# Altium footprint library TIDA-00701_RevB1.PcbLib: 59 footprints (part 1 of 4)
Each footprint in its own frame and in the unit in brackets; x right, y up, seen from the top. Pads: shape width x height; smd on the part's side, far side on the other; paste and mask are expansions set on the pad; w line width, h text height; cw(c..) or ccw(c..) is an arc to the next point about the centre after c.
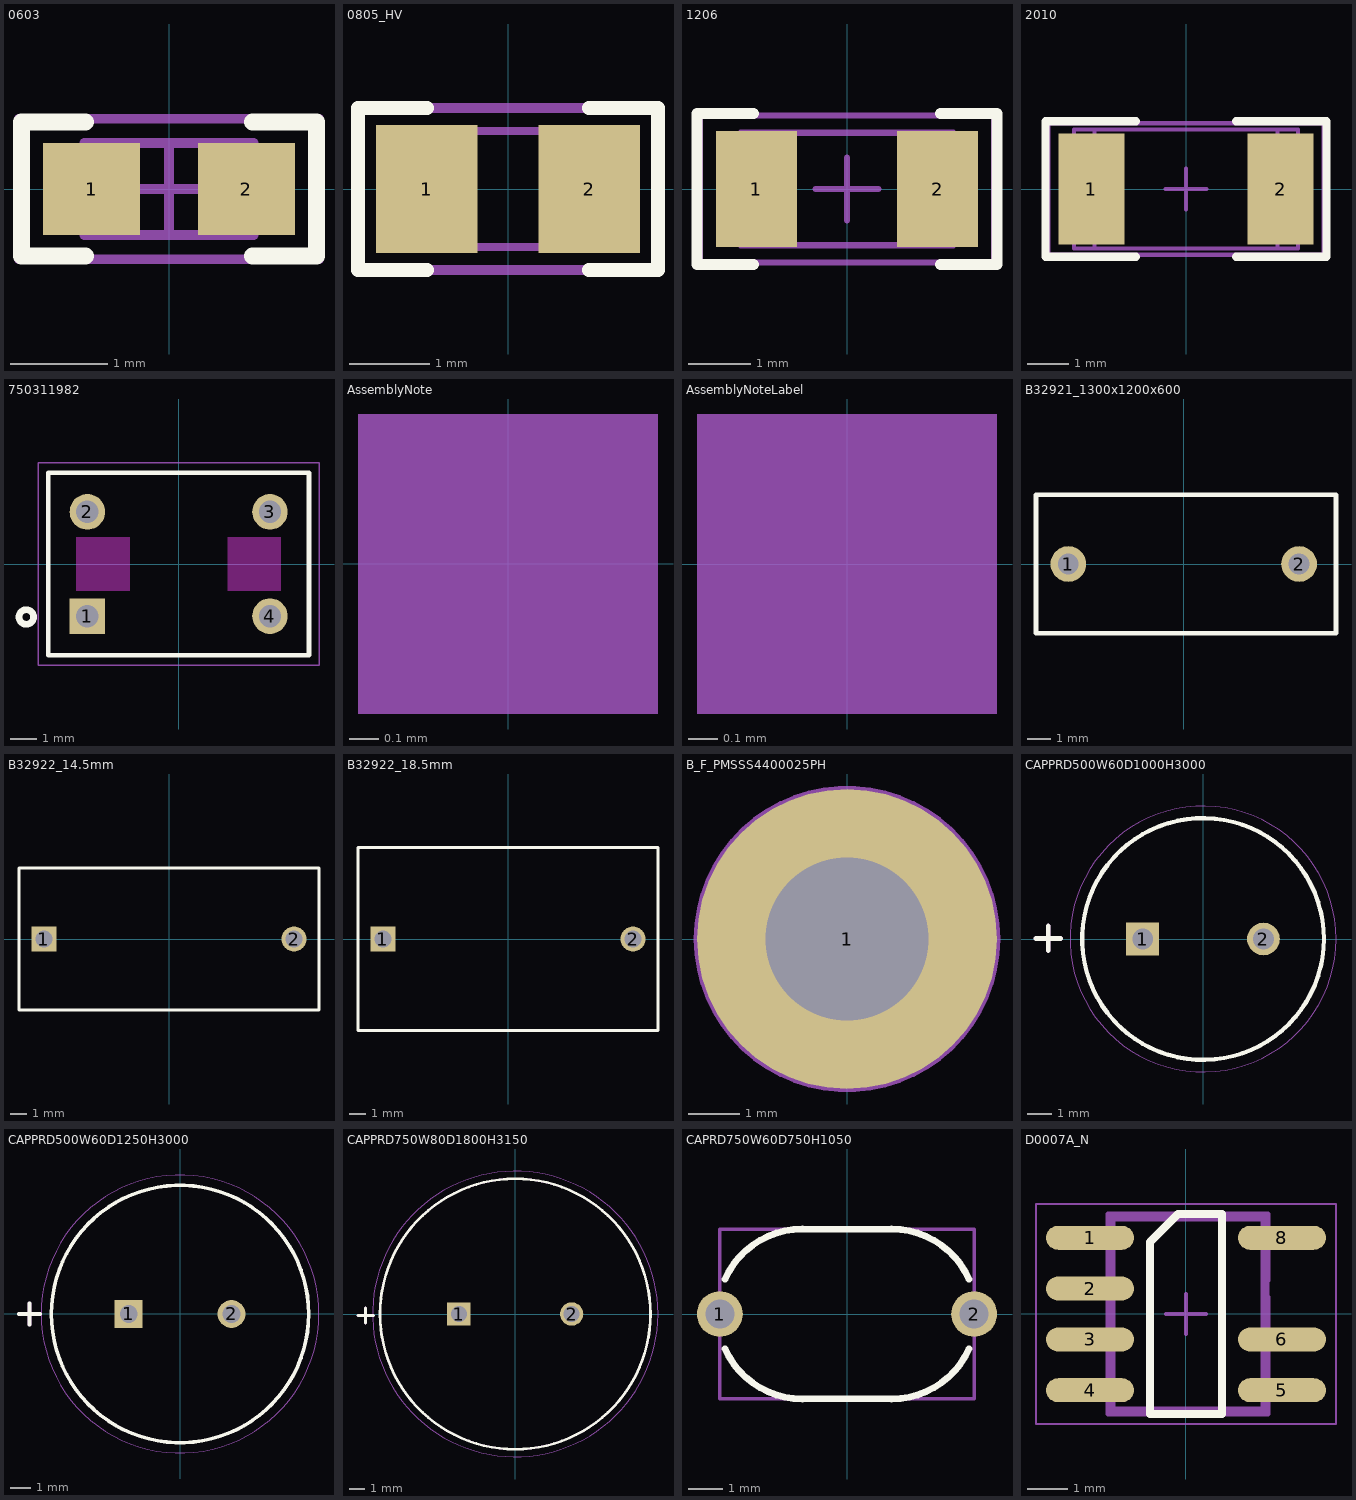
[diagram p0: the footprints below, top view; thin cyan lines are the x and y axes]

## 0603 [mm] "0603 from SM-752 data"
height 1
pads (2):
  rect 1x0.95 smd: 1(-0.8,0) 2(0.8,0)
Top Overlay:
  lines w0.178: -0.864,-0.691 -1.524,-0.691 -1.524,0.693 -0.864,0.693 ; 0.864,-0.691 1.524,-0.691 1.524,0.693 0.864,0.693
Mechanical 5:
  lines w0.1: -1.55,-0.725 -1.55,0.725 1.55,0.725 1.55,-0.725 -1.55,-0.725
  text ".Designator" at -1.168,-0.432 h0.86
Mechanical 13:
  lines w0.1: -0.55,-0.475 -0.55,0.475 ; 0.55,-0.475 0.55,0.475 ; -0.875,-0.475 0.875,-0.475 0.875,0.475 -0.875,0.475 -0.875,-0.475
Mechanical 15:
  lines w0.1: -0.475,0 0.475,0 ; 0,-0.475 0,0.475 ; -1.55,-0.725 1.55,-0.725 1.55,0.725 -1.55,0.725 -1.55,-0.725
3D body: height 1, standoff 0, extent -0.874,-0.474 -0.551,0.474
3D body: height 1, standoff 0, extent -0.549,-0.474 0.549,0.474
3D body: height 1, standoff 0, extent 0.551,-0.474 0.874,0.474

## 0805_HV [mil] "0805 with 30mil clearance between pads"
height 43.31
pads (2):
  rect 50x63 smd: 1(-40,0) 2(40,0)
Top Overlay:
  lines w7: -40,-40 -74,-40 -74,0 -74,40 -40,40 ; 40,-40 74,-40 74,0 74,40 40,40
Mechanical 5:
  lines w5: -74,-40 -74,40 74,40 74,-40 -74,-40
  text ".Designator" at 49,15 h35
Mechanical 13:
  lines w3.94: -25.59,-28.54 -25.59,28.54 ; 25.59,-28.54 25.59,28.54 ; -43.31,-28.54 43.31,-28.54 43.31,28.54 -43.31,28.54 -43.31,-28.54
3D body: height 43.31, standoff 0, extent -43.29,-28.52 -25.61,28.52
3D body: height 43.31, standoff 0, extent -25.57,-28.52 25.57,28.52
3D body: height 43.31, standoff 0, extent 25.61,-28.52 43.29,28.52

## 1206 [mm] "1206 from SM-752 data"
height 1.35
pads (2):
  rect 1.3x1.85 smd: 1(-1.45,0) 2(1.45,0)
Top Overlay:
  lines w0.178: -1.5,-1.21 -2.4,-1.21 -2.4,1.21 -1.5,1.21 ; 1.5,-1.21 2.4,-1.21 2.4,1.21 1.5,1.21
Mechanical 5:
  lines w0.1: -1.7,-0.9 1.7,-0.9 1.7,0.9 -1.7,0.9 -1.7,-0.9
  text ".Designator" at -1.194,-0.406 h0.89
Mechanical 13:
  lines w0.1: -1.2,-0.9 -1.2,0.9 ; 1.2,-0.9 1.2,0.9 ; -1.7,-0.9 1.7,-0.9 1.7,0.9 -1.7,0.9 -1.7,-0.9
Mechanical 15:
  lines w0.1: -0.5,0 0.5,0 ; 0,-0.5 0,0.5 ; -2.35,-1.175 2.35,-1.175 2.35,1.175 -2.35,1.175 -2.35,-1.175
3D body: height 1.35, standoff 0, extent -1.699,-0.899 -1.201,0.899
3D body: height 1.35, standoff 0, extent -1.199,-0.899 1.199,0.899
3D body: height 1.35, standoff 0, extent 1.201,-0.899 1.699,0.899

## 2010 [mm] "Chip Capacitor, Body 5.08x2.54mm, IPC Medium Density"
height 1.66
pads (2):
  rect 1.6x2.7 smd: 1(-2.3,0) 2(2.3,0)
Top Overlay:
  lines w0.2: -1.219,-1.65 -3.419,-1.65 -3.419,1.65 -1.219,1.65 ; 1.219,-1.65 3.419,-1.65 3.419,1.65 1.219,1.65
Mechanical 5:
  lines w0.1: -2.73,-1.45 -2.73,1.45 2.73,1.45 2.73,-1.45 -2.73,-1.45
  text ".Designator" at 0.152,-1.295 h0.89
Mechanical 13:
  lines w0.1: -2.23,-1.45 -2.23,1.45 ; 2.23,-1.45 2.23,1.45 ; -2.73,-1.45 2.73,-1.45 2.73,1.45 -2.73,1.45 -2.73,-1.45
Mechanical 15:
  lines w0.1: -0.5,0 0.5,0 ; 0,-0.5 0,0.5 ; -3.35,-1.6 3.35,-1.6 3.35,1.6 -3.35,1.6 -3.35,-1.6
3D body: height 1.66, standoff 0, extent -2.729,-1.449 -2.231,1.449
3D body: height 1.66, standoff 0, extent -2.229,-1.449 2.229,1.449
3D body: height 1.66, standoff 0, extent 2.231,-1.449 2.729,1.449

## 750311982 [mm] "4 LEAD,TH"
height 6.8
pads (4):
  rect 1.362x1.362 / inner round 1.362 / far side rect 1.362x1.362 hole 0.854: 1(-3.5,-2)
  round 1.362 hole 0.854: 2(-3.5,2) 3(3.5,2) 4(3.5,-2)
Top Layer keep-out:
  rectangle: 1.874,-1.027 3.928,1.027
  rectangle: -3.926,-1.027 -1.872,1.027
Top Overlay:
  circle w0.254: c-5.842,-2.032 r0.279
  lines w0.178: -5,-3.5 -5,3.5 5,3.5 5,-3.5 -5,-3.5
  text ".Designator" at -6.579,1.397 h0.89
Bottom Overlay:
  lines w0.178: -5,-3.5 -5,-2.5 ; -5,-1.5 -5,-0.5 ; -5,0.5 -5,1.5 ; -5,2.5 -5,3.5 ; -4.572,-3.5 -3.572,-3.5 ; -4.572,3.5 -3.572,3.5 ; -2.572,-3.5 -1.572,-3.5 ; -2.572,3.5 -1.572,3.5 ; -0.572,-3.5 0.428,-3.5 ; -0.572,3.5 0.428,3.5 ; 1.428,-3.5 2.428,-3.5 ; 1.428,3.5 2.428,3.5 ; 3.428,-3.5 4.428,-3.5 ; 3.428,3.5 4.428,3.5 ; 5,-3.5 5,-2.5 ; 5,-1.5 5,-0.5 ; 5,0.5 5,1.5 ; 5,2.5 5,3.5
Mechanical 5:
  lines w0.127: -5,-3.5 5,-3.5 5,3.5 -5,3.5 -5,-3.5
  text ".Designator" at -0.61,1.27 h0.89
Mechanical 15:
  lines w0.05: -5.381,-3.881 -5.381,3.881 5.381,3.881 5.381,-3.881 -5.381,-3.881
Mechanical 17:
  text "LEAD LENGTH:3 +/- 0.5MM" at -10.795,1.651 h1.02
3D body: height 6.8, standoff 0, extent -5,-3.5 5,3.5

## AssemblyNote [mm] "Assembly Note"
Mechanical 5:
  rectangle: -0.508,-0.508 0.508,0.508
  text ".Comment" at 1.143,-0.508 h1.02
  text ".Designator" at -4.191,-0.508 h1.02

## AssemblyNoteLabel [mm] "Assembly Note for PCB Labels"
Mechanical 5:
  rectangle: -0.508,-0.508 0.508,0.508
  text "Install label in silkscreened box after final wash.  Text shall be 8 pt font.  Text shall be per the Label Table in the PDF schematic." at 1.143,-0.508 h1.02
  text ".Designator" at -4.191,-0.508 h1.02

## B32921_1300x1200x600 [mm] "EPCOS"
height 12
pads (2):
  round 1.55 hole 0.9: 1(-5,0) 2(5,0)
Top Overlay:
  lines w0.203: -6.4,-3 6.6,-3 6.6,3 -6.4,3 -6.4,-3
Mechanical 5:
  lines w0.1: -6.4,-3 6.6,-3 6.6,3 -6.4,3 -6.4,-3
  text ".Designator" at 0.711,0.203 h0.89
3D body: height 1, standoff -3, extent 4.678,-0.324 5.325,0.325
3D body: height 1, standoff -3, extent -5.322,-0.324 -4.675,0.325
3D body: height 12, standoff 0, extent -6.399,-2.999 6.599,2.999

## B32922_14.5mm [mm] "Epcos film capacitors, 15mm spacing"
height 14.5
pads (2):
  rect 1.5x1.5 hole 1: 1(-7.5,0)
  round 1.5 hole 1: 2(7.5,0)
Top Overlay:
  lines w0.178: -9,-4.25 0,-4.25 9,-4.25 9,0 9,4.25 0,4.25 -9,4.25 -9,0 -9,-4.25
Mechanical 5:
  lines w0.127: -9,-4.25 -9,0 -9,4.25 0,4.25 9,4.25 9,0 9,-4.25 0,-4.25 -9,-4.25
  text ".Designator" at -0.584,-1.448 h1.02
3D body: height 14.5, standoff 0, extent -8.999,-4.249 8.999,4.249

## B32922_18.5mm [mm] "Epcos film capacitors, 15mm spacing"
height 18.5
pads (2):
  rect 1.5x1.5 hole 1: 1(-7.5,0)
  round 1.5 hole 1: 2(7.5,0)
Top Overlay:
  lines w0.178: -9,-5.5 -9,0 -9,5.5 0,5.5 9,5.5 9,0 9,-5.5 0,-5.5 -9,-5.5
Mechanical 5:
  lines w0.127: -9,-5.5 0,-5.5 9,-5.5 9,0 9,5.5 0,5.5 -9,5.5 -9,0 -9,-5.5
  text ".Designator" at -1.524,-0.508 h0.89
3D body: height 18.5, standoff 0, extent -8.999,-5.499 8.999,5.499

## B_F_PMSSS4400025PH [mil] "MACHINE SCREW PAN PHILLIPS 4-40"
height 82.68
pads (1):
  round 230 hole 125: 1(0,0)
Mechanical 5:
  circle w5: c0,0 r115
  text ".Designator" at -14,-19 h35
3D body: height 79.21, standoff -248.03, extent -109.49,-109.49 109.51,109.51

## CAPPRD500W60D1000H3000 [mm] "CAPACITOR, POLARIZED, 0.6MM LEAD DIA, PITCH 5MM"
height 31.5
pads (2):
  rect 1.354x1.354 / inner round 1.354 / far side rect 1.354x1.354 hole 0.854: 1(-2.5,0)
  round 1.354 hole 0.854: 2(2.5,0)
Top Overlay:
  circle w0.178: c0,0 r5
  lines w0.2: -6.909,0.025 -5.893,0.025 ; -6.401,-0.483 -6.401,0.533
  text ".Designator" at -5.563,-0.991 h0.89
Mechanical 5:
  circle w0.127: c0,0 r5
  lines w0.2: -6.909,0.025 -5.893,0.025 ; -6.401,-0.483 -6.401,0.533
  text ".Designator" at 0.711,0.254 h0.89
Mechanical 15:
  circle w0.05: c0,0 r5.5
3D body: height 31.5, standoff 0, extent -4.96,-4.99 5,4.99

## CAPPRD500W60D1250H3000 [mm] "CAPACITOR, POLARIZED, 0.6MM LEAD DIA, PITCH 5MM"
height 31.5
pads (2):
  rect 1.354x1.354 / inner round 1.354 / far side rect 1.354x1.354 hole 0.854: 1(-2.5,0)
  round 1.354 hole 0.854: 2(2.5,0)
Top Overlay:
  circle w0.178: c0,0 r6.25
  lines w0.2: -7.823,0 -6.807,0 ; -7.315,-0.508 -7.315,0.508
  text ".Designator" at -9.068,1.372 h0.89
Mechanical 5:
  circle w0.127: c0,0 r6.25
  lines w0.2: -7.823,0 -6.807,0 ; -7.315,-0.508 -7.315,0.508
  text ".Designator" at -1.524,-0.508 h0.89
Mechanical 15:
  circle w0.05: c0,0 r6.75
3D body: height 31.5, standoff 0, extent -6.201,-6.237 6.25,6.238

## CAPPRD750W80D1800H3150 [mm] "CAPACITOR, POLARIZED, 0.8MM LEAD DIA, PITCH 7.5MM"
height 33
pads (2):
  rect 1.554x1.554 / inner round 1.554 / far side rect 1.554x1.554 hole 1.054: 1(-3.75,0)
  round 1.554 hole 1.054: 2(3.75,0)
Top Overlay:
  circle w0.178: c0,0 r9
  lines w0.2: -10.465,-0.102 -9.449,-0.102 ; -9.957,-0.61 -9.957,0.406
  text ".Designator" at -10.71,2.97 h1.02
Mechanical 5:
  circle w0.127: c0,0 r9
  lines w0.2: -10.465,-0.102 -9.449,-0.102 ; -9.957,-0.61 -9.957,0.406
  text ".Designator" at -1.524,-0.508 h0.89
Mechanical 15:
  circle w0.05: c0,0 r9.5
3D body: height 33, standoff 0, extent -8.929,-8.982 9,8.982

## CAPRD750W60D750H1050 [mm] "Vishay BC Components"
height 10.5
pads (2):
  round 1.35 hole 0.85: 1(-3.75,0) 2(3.75,0)
Top Overlay:
  lines w0.2: -3.6,-1.025 ccw(c-1.316,-0.008) -1.316,-2.508 ; -3.6,1.025 cw(c-1.316,0.008) -1.316,2.508 ; -1.5,-2.5 1.5,-2.5 ; -1.5,2.5 1.5,2.5 ; 1.316,-2.508 ccw(c1.316,-0.008) 3.6,-1.025 ; 1.316,2.508 cw(c1.316,0.008) 3.6,1.025
Mechanical 5:
  lines w0.1: -3.75,-2.5 3.75,-2.5 3.75,2.5 -3.75,2.5 -3.75,-2.5
  text ".Designator" at -2.032,-0.508 h1.02
3D body: height 6, standoff -2, extent 3.453,-0.299 4.05,0.3
3D body: height 6, standoff -2, extent -4.047,-0.299 -3.45,0.3
3D body: height 10.49, standoff 3.01, extent -3.72,-2.5 3.75,2.5

## D0007A_N [mm] "SOIC, 7-Leads, Body 4.9x3.9mm, Pitch 1.27mm, IPC Medium Density"
height 1.75
pads (7):
  oval 2.2x0.6 smd: 1(-2.4,1.905) 2(-2.4,0.635) 3(-2.4,-0.635) 4(-2.4,-1.905) 5(2.4,-1.905) 6(2.4,-0.635) 8(2.4,1.905)
Top Overlay:
  lines w0.2: -0.9,-2.5 0.9,-2.5 0.9,2.5 -0.2,2.5 -0.9,1.8 -0.9,-2.5
Mechanical 5:
  lines w0.127: -1.95,-2.11 -1.95,-2.5 ; -1.95,-1.7 -1.95,-0.84 ; -1.95,-0.43 -1.95,0.43 ; -1.95,0.84 -1.95,1.7 ; -1.95,2.11 -1.95,2.5 ; 2.05,-2.11 2.05,-2.5 ; 2.05,-1.7 2.05,-0.84 ; 2.05,-0.43 2.05,0.43 2.03,0.43 2.03,0.84 2.05,0.84 2.05,1.7 ; 2.05,2.11 2.05,2.5 ; -2.325,-2.11 -2.39,-2.11 -2.95,-2.11 -2.95,-1.7 -2.39,-1.7 -2.325,-1.7 ; -2.325,-2.11 -2.045,-2.11 -1.931,-2.11 -1.931,-1.7 -2.045,-1.7 -2.325,-1.7 ; -2.325,-2.11 -2.325,-1.7 ; -2.325,-0.84 -2.39,-0.84 -2.95,-0.84 -2.95,-0.43 -2.39,-0.43 -2.325,-0.43 ; -2.325,-0.84 -2.045,-0.84 -1.931,-0.84 -1.931,-0.43 -2.045,-0.43 -2.325,-0.43 ; -2.325,-0.84 -2.325,-0.43 ; -2.325,0.43 -2.325,0.84 ; -2.325,0.43 -2.39,0.43 -2.95,0.43 -2.95,0.84 -2.39,0.84 -2.325,0.84 ; -2.325,0.43 -2.045,0.43 -1.931,0.43 -1.931,0.84 -2.045,0.84 -2.325,0.84 ; -2.325,1.7 -2.39,1.7 -2.95,1.7 -2.95,2.11 -2.39,2.11 -2.325,2.11 ; -2.325,1.7 -2.325,2.11 ; -2.325,1.7 -2.045,1.7 -1.931,1.7 -1.931,2.11 -2.045,2.11 -2.325,2.11 ; -1.95,-2.5 -1.822,-2.372 ; -1.95,-2.5 2.05,-2.5 ; -1.95,2.5 2.05,2.5 ; -1.95,2.5 -1.822,2.372 ; -1.822,-2.372 1.922,-2.372 ; -1.822,-2.372 -1.822,2.372 ; -1.822,2.372 1.922,2.372 ; 1.922,-2.372 2.05,-2.5 ; 1.922,-2.372 1.922,2.372 ; 1.922,2.372 2.05,2.5 ; 2.425,-2.11 2.425,-1.7 ; 2.425,-2.11 2.145,-2.11 2.031,-2.11 2.031,-1.7 2.145,-1.7 2.425,-1.7 ; 2.425,-2.11 2.49,-2.11 3.05,-2.11 3.05,-1.7 2.49,-1.7 2.425,-1.7 ; 2.425,-0.84 2.425,-0.43 ; 2.425,-0.84 2.145,-0.84 2.031,-0.84 2.031,-0.43 2.145,-0.43 2.425,-0.43 ; 2.425,-0.84 2.49,-0.84 3.05,-0.84 3.05,-0.43 2.49,-0.43 2.425,-0.43 ; 2.425,1.7 2.425,2.11 ; 2.425,1.7 2.145,1.7 2.031,1.7 2.031,2.11 2.145,2.11 2.425,2.11 ; 2.425,1.7 2.49,1.7 3.05,1.7 3.05,2.11 2.49,2.11 2.425,2.11
  text ".Designator" at -0.572,0.989 h0.89
Mechanical 15:
  lines w0.05: -3.75,-2.75 -3.75,2.75 3.75,2.75 3.75,-2.75 -3.75,-2.75
  lines w0.1: -0.5,0 0.5,0 ; 0,-0.5 0,0.5
3D body: height 1.54, standoff -0.01, extent -3,-2.5 3,2.5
